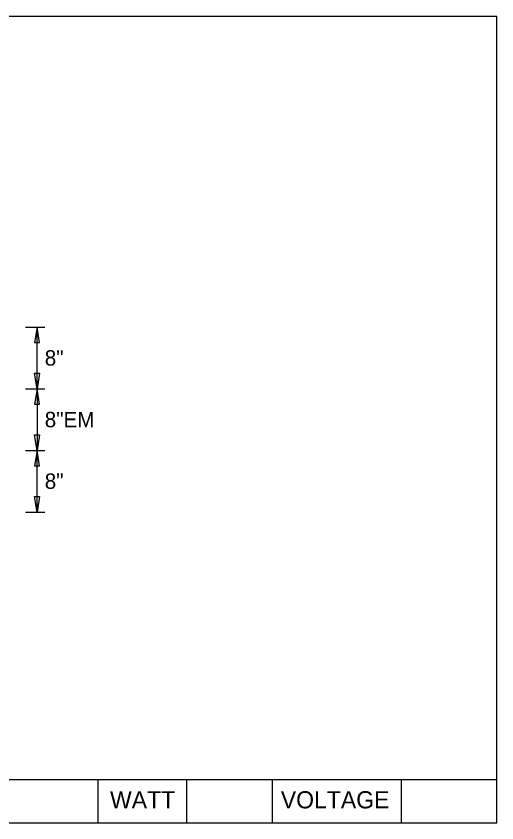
# Model space of a CAD drawing. Extents: x 1374 to 1480, y 568 to 638.
# Drawn here: x 1422.97 to 1428.16, y 578.92 to 587.64 of the extents above; entities that cross this region are included whole.
import ezdxf

# ---------------------------------------------------------------- set-up
doc = ezdxf.new("R2010")
doc.units = 0
for name, color, linetype in [('GSDims', 7, 'Continuous'), ('SheetLinesMisc2_dp', 7, 'Continuous'), ('TextMinor', 7, 'Continuous')]:
    doc.layers.add(name, color=color, linetype=linetype)

msp = doc.modelspace()

# ---------------------------------------------------------------- linework, layer by layer
at = {"layer": 'GSDims'}
for p, q in [((1423.0664, 584.2826), (1423.2747, 584.2826)), ((1423.0664, 584.2826), (1423.0664, 584.2826)), ((1423.1914, 583.6159), (1423.1914, 584.2826)), ((1423.0664, 583.6159), (1423.2747, 583.6159)), ((1423.0664, 583.6159), (1423.2747, 583.6159)), ((1423.1914, 583.6159), (1423.1914, 582.9492)), ((1423.0664, 582.9492), (1423.2747, 582.9492)), ((1423.0664, 582.9492), (1423.2747, 582.9492)), ((1423.1914, 582.2826), (1423.1914, 582.9492)), ((1423.0664, 582.2826), (1423.2747, 582.2826)), ((1423.0664, 582.2826), (1423.0664, 582.2826))]:
    msp.add_line(p, q, dxfattribs=at)
for points in [[(1423.1914, 584.2826), (1423.1636, 584.1159), (1423.2192, 584.1159)], [(1423.1914, 583.6159), (1423.1636, 583.7826), (1423.2192, 583.7826)], [(1423.1914, 583.6159), (1423.1636, 583.4492), (1423.2192, 583.4492)], [(1423.1914, 582.9492), (1423.1636, 583.1159), (1423.2192, 583.1159)], [(1423.1914, 582.9492), (1423.1636, 582.7826), (1423.2192, 582.7826)], [(1423.1914, 582.2826), (1423.1636, 582.4492), (1423.2192, 582.4492)]]:
    msp.add_lwpolyline(points, close=True, dxfattribs=at)
at = {"layer": 'SheetLinesMisc2_dp'}
for p, q in [((1410.2555, 587.644), (1428.1633, 587.644)), ((1428.1632, 578.9337), (1428.1632, 587.6446)), ((1410.2556, 579.3887), (1428.1633, 579.3887)), ((1423.8473, 579.3887), (1423.8473, 578.9214)), ((1424.808, 579.3887), (1424.808, 578.9214)), ((1425.7344, 579.3887), (1425.7344, 578.9214)), ((1427.1292, 579.3887), (1427.1292, 578.9214)), ((1410.2556, 578.9214), (1428.1633, 578.9214)), ((1428.1632, 578.9219), (1428.1632, 578.9337))]:
    msp.add_line(p, q, dxfattribs=at)

# ---------------------------------------------------------------- texts
at = {"layer": 'GSDims'}
for s, p in [('8"', (1423.2747, 583.8659)), ('8"EM', (1423.2747, 583.1992)), ('8"', (1423.2747, 582.5326))]:
    msp.add_text(s, height=0.16667, dxfattribs=at).set_placement(p)
at = {"layer": 'TextMinor'}
for s, p in [('WATT', (1423.9805, 579.0779)), ('VOLTAGE', (1425.8272, 579.0779))]:
    msp.add_text(s, height=0.18601, dxfattribs=at).set_placement(p)

doc.saveas('drawing.dxf')
